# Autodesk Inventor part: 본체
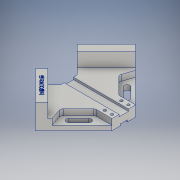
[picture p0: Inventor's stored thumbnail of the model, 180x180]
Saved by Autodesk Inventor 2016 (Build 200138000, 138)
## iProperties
Created: 2019-04
Part Number: 본체
Material: 알루미늄 6061
Document SubType Name: Modeling
Designer: 605-06
Density: 2.7 g/cm^3
Appearance: 알루미늄 - 평지
Mass: 601.509 g
Surface Area: 426.536 cm^2
Volume: 222.781 cm^3
Author: 605-06
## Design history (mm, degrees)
sketch "스케치1"
  geometry: L1 (84.853, -24.33)-(35.355, -73.827); L2 (20, 40.523)-(84.853, -24.33); L3 (0, -109.183)-(0, 60.523); L4 (35.355, -73.827)-(15.47, -53.941); L5 (11.934, -52.477)-(0, -52.477); L6 (20, 40.523)-(0, 40.523); A1 r 5 centre (11.934, -57.477) between (15.47, -53.941) and (11.934, -52.477); 2 further points
  constraints: 12 end point, 5 point on line, 2 perpendicular, 2 point on circle, 2 tangent, 1 centre point, 1 vertical
  dimensions: "d1" = 90 deg angle of L2 L1; "d4" = 120 distance of L1.start L3.start; "d5" = 120 distance of L3.end L1.start; "d6" = 50 distance of L1.end L3.start; "d7" = 40 diameter of L2.start L3; "d8" = 45 deg angle of L3 L1; "d9" = 93 distance between parallel lines of L5 L6; "d10" = 90 deg angle of L4 L1; "d49" = 5 radius of A1
extrude "돌출1" new body sketch "스케치1" distance "d11" = 18; taper "d12" = 0 deg
sketch "스케치2"
  geometry: L1 (-15.47, 53.941)-(-35.355, 73.827) reference; L2 (-84.853, 24.33)-(-20, -40.523) reference; L3 (-74.246, 13.723)-(-24.749, 63.221); L4 (-84.853, 24.33)-(-35.355, 73.827) reference; 2 further points
  constraints: 2 end point, 2 point on line, 1 perpendicular
  dimensions: "d14" = 15 distance between parallel lines of L4 L3
extrude "돌출2" join sketch "스케치2" distance "d15" = 24; taper "d16" = 0 deg
sketch "스케치3"
  geometry: L1 (-74.246, 13.723)-(-20, -40.523) reference; L2 (-70.711, 10.188)-(-52.429, 16.281); L3 (-47.312, 15.074)-(-21.464, -10.774); L4 (-20, -14.31)-(-20, -40.523); L5 (-35.355, 73.827)-(-84.853, 24.33) reference; L6 (-49.497, 3.117)-(-32.527, -13.854); L7 (-49.497, 3.117)-(-32.527, -13.854); L8 (-52.679, -0.065)-(-35.709, -17.036); L9 (-29.345, -10.672)-(-46.315, 6.299); A1 r 4.5 centre (-49.497, 3.117) between (-46.315, 6.299) and (-52.679, -0.065); A2 r 4.5 centre (-32.527, -13.854) between (-35.709, -17.036) and (-29.345, -10.672); A3 r 5 centre (-50.848, 11.538) between (-47.312, 15.074) and (-52.429, 16.281); A4 r 5 centre (-25, -14.31) between (-20, -14.31) and (-21.464, -10.774); 3 further points
  constraints: 16 end point, 8 point on circle, 8 tangent, 4 centre point, 3 parallel, 3 point on line, 1 collinear, 1 midpoint, 1 vertical
  dimensions: "d17" = 20 distance between parallel lines of L3 L1; "d18" = 20 distance from line of L2.start L5; "d19" = 30 distance from line of point (-49.497, 17.259) L5; "d20" = 9 diameter of A2; "d21" = 24 distance of L6.start L6.end; "d22" = 40 distance from line of L5 L6.start; "d23" = 10 distance between parallel lines of L6 L1; "d24" = 5 radius of A3; "d25" = 5 radius of A4
extrude "돌출3" cut sketch "스케치3" distance "d26" = 10; taper "d27" = 0 deg
extrude "돌출4" cut sketch "스케치3" stored distance "d28" = 10; taper "d29" = 0 deg
sketch "스케치5"
  geometry: L1 (0, -52.477)-(0, 40.523) reference; L2 (0, 40.523)-(-20, 40.523) reference; 3 further points
  constraints: 1 vertical alignment
  dimensions: "d33" = 14 distance from line of L1 point (-14, 34.523); "d34" = 6 distance from line of L2 point (-14, 34.523); "d35" = 12 distance of point (-14, 34.523) point (-14, 22.523)
hole "구멍1" sketch "스케치5" at (-14, 34.523), (-14, 22.523) diameter "d36" = 4.5; stored, may be unused: countersink angle "d40" = 90 deg, drill point angle "d42" = 118 deg; dims "d37" = 6, "d38" = 8, "d39" = 10, "d41" = 8
sketch "스케치6"
  geometry: L1 (-11.934, 52.477)-(0, 52.477) reference; L2 (-8, 52.477)-(-8, -40.523); L3 (-20, -40.523)-(0, -40.523) reference; L4 (0, -40.523)-(0, 52.477) reference; 2 further points
  constraints: 2 end point, 2 point on line, 1 vertical
  dimensions: "d43" = 8 distance between parallel lines of L4 L2
extrude "돌출5" cut sketch "스케치6" distance "d44" = 3.5; taper "d45" = 0 deg
sketch "스케치7"
  geometry: L1 (0, 40.523)-(-20, 40.523) reference; L2 (-6, 40.523)-(-6, -52.477); L3 (-8, -52.477)-(0, -52.477) reference; L4 (0, -52.477)-(0, 40.523) reference; 1 further point
  constraints: 2 end point, 2 point on line, 1 vertical
  dimensions: "d46" = 6 distance between parallel lines of L4 L2
extrude "돌출6" cut sketch "스케치7" distance "d47" = 3; taper "d48" = 0 deg
sketch "스케치8"
  geometry: L1 (-84.853, 24.33)-(-74.246, 13.723) reference; L2 (-24.749, 63.221)-(-35.355, 73.827) reference; L3 (-35.355, 73.827)-(-84.853, 24.33) reference; 2 further points
  constraints: 1 other
  dimensions: "d53" = 35 distance from line of point (-54.801, 43.775) L2; "d54" = 7.5 distance from line of L3 point (-54.801, 43.775)
feature "엠보싱1" sketch "스케치8" dims "d1" = 90 deg, "d4" = 120, "d5" = 120, "d6" = 50, "d7" = 40, "d8" = 45 deg, "d9" = 93, "d10" = 90 deg, "d49" = 5, "d55" = 0.5, "d56" = 0
node "솔리드1"
mirror "대칭3"
